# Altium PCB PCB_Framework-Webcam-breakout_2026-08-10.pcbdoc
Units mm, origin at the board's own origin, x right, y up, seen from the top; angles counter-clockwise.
Board outline 121.3 x 50.8 mm, 2 copper layers (Top Layer, Bottom Layer); 9 components, 13 nets, 55 pads, 11 vias.
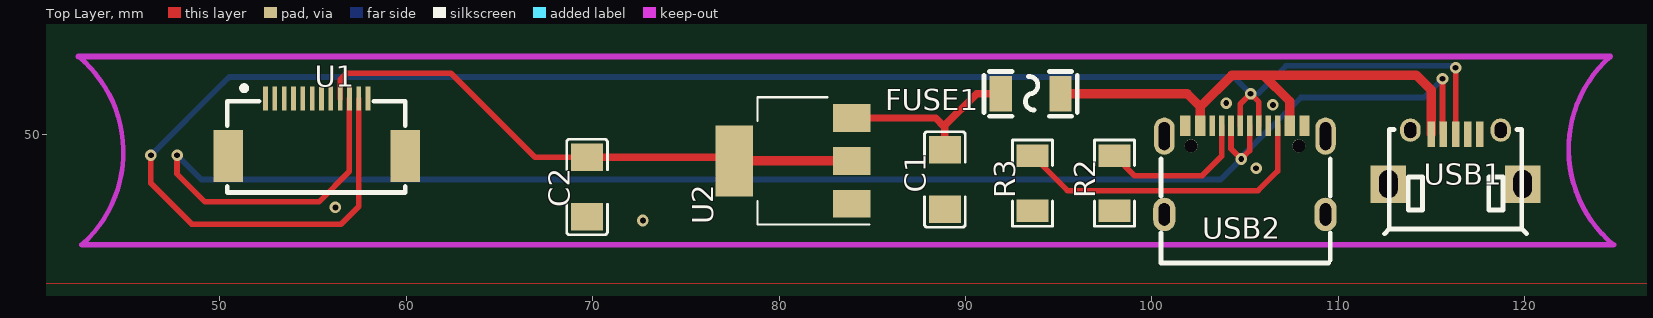
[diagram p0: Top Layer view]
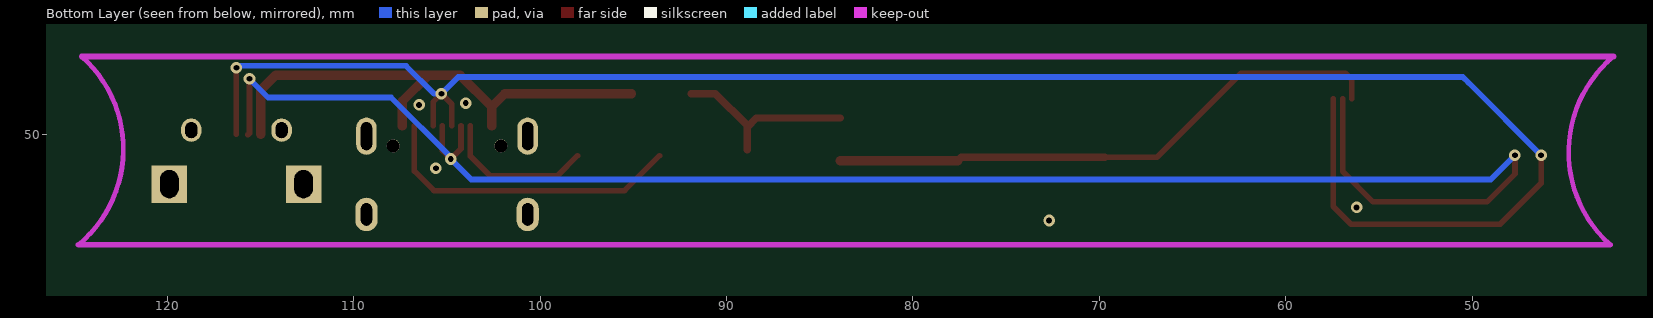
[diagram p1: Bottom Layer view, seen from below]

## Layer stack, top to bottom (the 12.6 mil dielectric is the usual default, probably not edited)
Top Layer: signal copper (thickness not stored)
Dielectric: dielectric 0.32, FR-4, Dk 4.8
Bottom Layer: signal copper (thickness not stored)

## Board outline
146.7,25.4 25.4,25.4 25.4,76.2 146.7,76.2

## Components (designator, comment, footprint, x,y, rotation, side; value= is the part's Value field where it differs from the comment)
C1 "100nF" C1206 88.9,47.6 r90 top
C2 "100nF" C1206 69.7,47.2 r90 top
FUSE1 "SMD1206P035TF" F1206 93.5,52.2 r180 top
R2 "5.1kΩ" R1206 98,47.4 r90 top
R3 "5.1kΩ" R1206 93.6,47.4 r90 top
U1 "KH-FPC0.5-H2.0SMT-12P-QCHF" FPC-SMD_12P-P0.50_KH-FPC0.5-H2.0SMT-12P-QCHF 55.2,50.4 r0 top
U2 "LD1117S33TR" SOT-223 77.6,48.6 r180 top
USB1 "U254-051T-4BH23-S2S" MICRO-USB-2.0-5P-5.6X7.15-H3.05-TE 116.3,48.8 r0 top
USB2 "TYPE-C 16PIN 2MD(073)" USB-C-SMD_TYPE-C-6PIN-2MD-073 105,48.1 r0 top

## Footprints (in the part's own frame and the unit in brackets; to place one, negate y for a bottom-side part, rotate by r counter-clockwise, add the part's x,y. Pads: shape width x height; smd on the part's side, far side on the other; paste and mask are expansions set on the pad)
C1206 [mm]
  rect 1.485x1.728 smd paste-100 mask+0.051: 1(-1.593,0) 2(1.593,0)
  silkscreen extent -2.56,-1.09 2.56,1.09
F1206 [mm]
  rect 1.2x1.9 smd paste+0 mask+0.102: 1(-1.6,0) 2(1.6,0)
  silkscreen extent -2.5,-1.2 2.5,1.2
FPC-SMD_12P-P0.50_KH-FPC0.5-H2.0SMT-12P-QCHF [mm]
  rect 0.25x1.3 smd paste+0 mask+0.05: 1(-2.75,1.541) 2(-2.25,1.541) 3(-1.75,1.541) 4(-1.25,1.541) 5(-0.75,1.541) 6(-0.25,1.541) 7(0.25,1.541) 8(0.75,1.541) 9(1.25,1.541) 10(1.75,1.541) 11(2.25,1.541) 12(2.75,1.541)
  rect 1.6x2.8 smd paste+0 mask+0.05: 13(-4.75,-1.541) 14(4.75,-1.541)
  silkscreen extent -4.8,-3.5 4.75,2.24
MICRO-USB-2.0-5P-5.6X7.15-H3.05-TE [mm]
  rect 0.4x1.35 smd paste+0 mask+0.051: 1(-1.3,1.225) 2(-0.65,1.225) 3(0,1.225) 4(0.65,1.225) 5(1.3,1.225)
  oval 1.1x1.25 hole 0.65 slot 0.85 at 90 deg paste+0 mask+0.051: 6(2.425,1.45) 9(-2.425,1.45)
  rect 1.9x2 hole 1 slot 1.5 at 90 deg paste+0 mask+0.051: 7(3.6,-1.45) 8(-3.6,-1.45)
  silkscreen extent -3.81,-4.11 3.81,1.48
R1206 [mm]
  rect 1.208x1.701 smd paste-100 mask+0.051: 1(-1.479,0) 2(1.479,0)
  silkscreen extent -2.31,-1.08 2.31,1.08
SOT-223 [mm]
  rect 2x1.5 smd paste+0 mask+0.051: 1(-6.3,2.3) 2(-6.3,0) 3(-6.3,-2.3)
  rect 2x3.8 smd paste+0 mask+0.051: 4(0,0)
  silkscreen extent -7.25,-3.41 -1.24,3.41
USB-C-SMD_TYPE-C-6PIN-2MD-073 [mm]
  rect 0.55x1.1 smd paste-100 mask+0.05: 1(-3.2,2.375) 2(-2.4,2.375) 11(2.4,2.375) 12(3.2,2.375)
  rect 0.3x1.1 smd paste-100 mask+0.05: 3(-1.75,2.375) 4(-1.25,2.375) 5(-0.75,2.375) 6(-0.25,2.375) 7(0.25,2.375) 8(0.75,2.375) 9(1.25,2.375) 10(1.75,2.375)
  oval 1.2x1.8 hole 0.6 slot 1.2 at 90 deg paste+0 mask+0.05: 13(-4.325,-2.375) 14(4.325,-2.375)
  oval 1.1x2 hole 0.6 slot 1.5 at 90 deg paste+0 mask+0.05: 13(-4.325,1.825) 14(4.325,1.825)
  round 0.7 hole 0.7 unplated paste+0: ""(-2.89,1.305) ""(2.89,1.305)
  silkscreen extent -4.5,-4.97 4.57,0.6

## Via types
v1: diameter 0.62, hole 0.31, Top Layer to Bottom Layer, tented both sides, 11 vias

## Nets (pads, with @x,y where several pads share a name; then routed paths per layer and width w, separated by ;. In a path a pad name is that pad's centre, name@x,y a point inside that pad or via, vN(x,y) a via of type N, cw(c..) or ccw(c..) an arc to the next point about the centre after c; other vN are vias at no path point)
3.3V: C2.2 U1.9 U2.2 U2.4 | length 30.6
  Top Layer w0.3: U1.9 56.45,52.95 56.8,53.3 62.4,53.3 66.907,48.793 C2.2
  Top Layer w0.4: C2.2 77.407,48.793 U2.4
  Top Layer w0.5: U2.4 U2.2
C1_2: C1.2 FUSE1.2 U2.3 | length 11.4
  Top Layer w0.4: U2.3 88.4,50.899 88.9,50.399 C1.2 88.9,50.5 90.6,52.2 FUSE1.2
GND: C1.1 C2.1 R2.1 R3.1 U1.1 U1.12 U1.13 U1.14 U2.1 USB1.5 USB1.6 USB1.7 USB1.8 USB1.9 USB2.1 USB2.12 USB2.13 USB2.14
  other v1: 72.7,45.4 56.2,46.1 105.6,48.2 106.5,51.6 104,51.7
S$74: 
S$76: 
S$78: 
S$4931: 
S$4935: 
U1_10: U1.10 USB1.2 USB2.5 USB2.7 | length 93.2
  Top Layer w0.3: v1(47.7,48.9) 47.699,47.899 49.2,46.401 55.309,46.401 56.95,48.042 U1.10 ; USB2.5 104.25,49.25 v1(104.8,48.7) 105.25,49.15 USB2.7 ; v1(115.6,53) 115.6,50.075 USB1.2 ; USB1.2@115.65,50.05 USB1.2@115.7,50
  Bottom Layer w0.3: v1(47.7,48.9) 49,47.6 103.7,47.6 v1(104.8,48.7) 104.8,48.8 108,52 114.6,52 v1(115.6,53)
U1_11: U1.11 USB1.3 USB2.6 USB2.8 | length 100
  Top Layer w0.3: v1(46.3,48.9) 46.299,47.399 48.499,45.199 56.5,45.199 57.45,46.149 U1.11 ; USB2.6 104.75,51.65 v1(105.3,52.2) 105.75,51.75 USB2.8 ; USB1.3 v1(116.3,53.6)
  Bottom Layer w0.3: v1(46.3,48.9) 50.201,52.799 50.5,53.1 104.4,53.1 v1(105.3,52.2) 105.7,52.2 107.2,53.7 116.2,53.7 v1(116.3,53.6)
USB2_2: FUSE1.1 USB1.1 USB2.2 USB2.11 | length 29
  Top Layer w0.5: FUSE1.1 101.9,52.2 102.6,51.5 ; 105.994,53.2 107.4,51.794 USB2.11 ; USB1.1 115,52.4 114.2,53.2 104.3,53.2 102.6,51.5 ; 102.6,51.5 USB2.2 102.6,51.5
USB2_4: R2.2 USB2.4 | length 8.3
  Top Layer w0.3: R2.2 99.079,47.8 102.7,47.8 103.75,48.85 USB2.4
USB2_10: R3.2 USB2.10 | length 16.8
  Top Layer w0.3: R3.2 95.479,47 105.7,47 106.751,48.049 USB2.10
pads on no net: U1.2 U1.3 U1.4 U1.5 U1.6 U1.7 U1.8 USB1.4 USB2. USB2.3 USB2.9

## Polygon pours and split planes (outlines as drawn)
GND on Bottom Layer (solid): 38.1,63.5 133.5,63.5 134,63 134,39.9 134,38.1 132.2,38.1 39.6,38.1 38.1,39.6
GND on Top Layer (solid): 39.7,59.1 128.2,59.1 128,42 39.6,42

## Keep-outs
Keep-Out Layer:
  lines w0.254: 42.413,54.2 cw(c38.159,49.074) 42.65,44.153 ; 124.6,54.2 ccw(c129.029,49.225) 124.775,44.098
